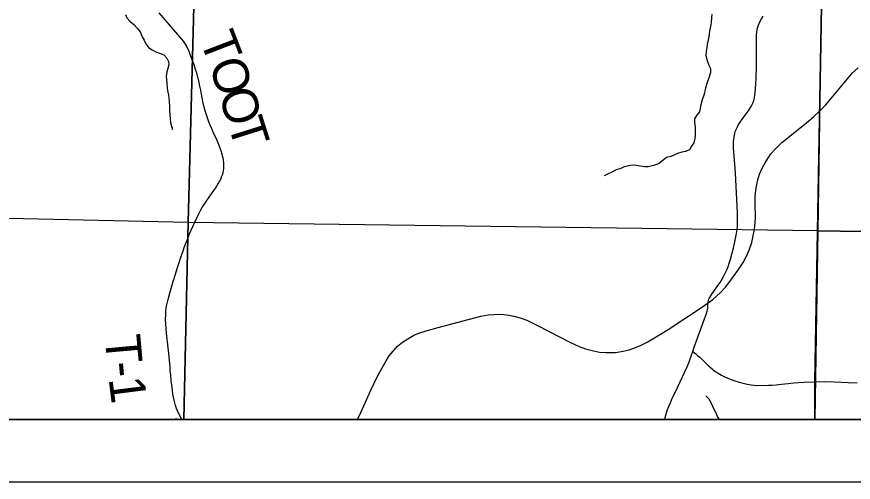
# Model space of a CAD drawing. Extents: x 0 to 34, y 0 to 22.
# Drawn here: x 15.148 to 16.483, y 13.5 to 14.243 of the extents above; entities that cross this region are included whole.
import ezdxf

# ---------------------------------------------------------------- set-up
doc = ezdxf.new("R2010")
doc.units = 0
for name, color, linetype in [('GM_X_Corporation', 7, 'Continuous'), ('GM_X_County_Road', 7, 'Continuous'), ('GM_X_Minor_River', 7, 'Continuous'), ('GM_X_Rail_Line', 7, 'Continuous'), ('GM_X_Township_Road', 7, 'Continuous'), ('GM_X_Township_Road_Text', 7, 'Continuous'), ('SH_Data', 7, 'Continuous')]:
    doc.layers.add(name, color=color, linetype=linetype)

msp = doc.modelspace()

# ---------------------------------------------------------------- linework, layer by layer
at = {"layer": 'GM_X_Corporation'}
for points in [[(16.4214, 13.6), (17.4, 13.6), (17.4, 16.913), (16.5516, 16.9243), (16.4689, 16.9245), (16.4603, 16.2617), (16.4611, 16.1288), (16.4516, 15.5964), (16.4498, 15.4626), (16.4419, 14.8642), (16.438, 14.5908), (16.4339, 14.3806), (16.4212, 13.6609)], [(14.443, 14.9501), (15.4475, 14.9085), (15.4212, 13.9143), (14.4181, 13.9369)], [(15.4475, 14.9085), (16.441, 14.8856), (16.4262, 13.901), (15.4212, 13.9143)], [(17.4, 13.8871), (17.4, 14.8906), (16.441, 14.8856), (16.4262, 13.901)], [(14.411, 13.6), (15.4145, 13.6), (15.4212, 13.9143), (14.4181, 13.9369)], [(15.4145, 13.6), (16.4212, 13.6), (16.4262, 13.901), (15.4212, 13.9143)], [(16.4212, 13.6), (17.4, 13.6), (17.4, 13.8871), (16.4262, 13.901)]]:
    msp.add_lwpolyline(points, close=True, dxfattribs=at)
msp.add_lwpolyline([(10.9052, 15.3502), (10.897, 14.5214), (10.8818, 13.7678), (10.8788, 13.6), (16.4214, 13.6), (16.4212, 13.6609), (16.4339, 14.3806), (16.438, 14.5908), (16.4419, 14.8642), (16.4498, 15.4626)], dxfattribs=at)
at = {"layer": 'GM_X_County_Road'}
msp.add_lwpolyline([(16.1817, 13.6), (16.1826, 13.6034), (16.1859, 13.6143), (16.1882, 13.6207), (16.1907, 13.6268), (16.1944, 13.6352), (16.1982, 13.6433), (16.2177, 13.6844), (16.2201, 13.6904), (16.222, 13.6953), (16.2235, 13.6995), (16.2251, 13.7043), (16.2265, 13.7086), (16.2289, 13.7154), (16.2453, 13.7606), (16.247, 13.7653), (16.2483, 13.7693), (16.2495, 13.7731), (16.2499, 13.7749), (16.2503, 13.7776), (16.2506, 13.78), (16.2507, 13.7858), (16.2514, 13.7898), (16.2523, 13.7924), (16.2533, 13.7945), (16.254, 13.7959), (16.2568, 13.8002), (16.262, 13.8075), (16.2666, 13.814), (16.27, 13.819), (16.2721, 13.8223), (16.275, 13.8273), (16.2776, 13.8324), (16.2812, 13.8403), (16.2829, 13.8445), (16.2848, 13.8495), (16.2868, 13.8559), (16.289, 13.8638), (16.2916, 13.8738), (16.2937, 13.8834), (16.2964, 13.8969), (16.2974, 13.9033), (16.2978, 13.9085), (16.298, 13.9113), (16.298, 13.9229), (16.2979, 13.9305), (16.2947, 13.9932), (16.2942, 14.0008), (16.2917, 14.0334), (16.2916, 14.036), (16.2917, 14.0443), (16.2919, 14.0469), (16.2924, 14.0511), (16.2934, 14.0563), (16.2944, 14.0595), (16.2955, 14.0627), (16.2971, 14.0662), (16.299, 14.0697), (16.301, 14.073), (16.3069, 14.0813), (16.3147, 14.092), (16.3172, 14.0955), (16.3189, 14.0982), (16.3208, 14.1017), (16.3222, 14.1051), (16.3237, 14.1093), (16.3248, 14.1136), (16.3255, 14.1177), (16.3259, 14.1214), (16.327, 14.1356), (16.3275, 14.1453), (16.328, 14.1622), (16.3281, 14.1968), (16.3284, 14.2141), (16.3288, 14.2186), (16.3298, 14.2246), (16.3313, 14.2295), (16.3322, 14.232), (16.3334, 14.2347), (16.3361, 14.2397), (16.3388, 14.244)], dxfattribs=at)
at = {"layer": 'GM_X_Minor_River'}
msp.add_line((15.3999, 13.6), (15.4026, 13.6022), dxfattribs=at)
for points in [[(15.3209, 14.2463), (15.3233, 14.241), (15.3284, 14.2355), (15.3346, 14.2307), (15.3397, 14.2247), (15.3444, 14.2188), (15.348, 14.2109), (15.3508, 14.2052), (15.3536, 14.1996), (15.3579, 14.194), (15.3637, 14.1899), (15.3694, 14.187), (15.3756, 14.1845), (15.3821, 14.182), (15.3871, 14.1768), (15.3899, 14.1712), (15.3904, 14.1659), (15.3887, 14.1601), (15.3873, 14.1548), (15.3863, 14.1479), (15.3865, 14.1426), (15.387, 14.1357), (15.3875, 14.1304), (15.3884, 14.1244), (15.3897, 14.1183), (15.3907, 14.1077), (15.3913, 14.0997), (15.3915, 14.0932), (15.392, 14.0864), (15.3926, 14.0792), (15.3931, 14.0739), (15.3947, 14.0682), (15.396, 14.0629), (15.3962, 14.0667)], [(16.2569, 14.2469), (16.2562, 14.2416), (16.256, 14.2339), (16.2547, 14.2271), (16.2533, 14.2206), (16.2527, 14.2152), (16.2511, 14.2049), (16.2493, 14.1992), (16.2487, 14.1938), (16.2477, 14.1873), (16.2471, 14.1808), (16.2496, 14.1729), (16.252, 14.1654), (16.2548, 14.1601), (16.255, 14.1536), (16.2529, 14.1467), (16.2486, 14.1345), (16.2465, 14.1268), (16.2448, 14.1195), (16.2416, 14.1103), (16.2396, 14.1023), (16.2382, 14.0969), (16.2372, 14.0912), (16.2324, 14.0854), (16.2291, 14.08), (16.2293, 14.0739), (16.2302, 14.0674), (16.2303, 14.0606), (16.2301, 14.0545), (16.2299, 14.0488), (16.2282, 14.0415), (16.2245, 14.0361), (16.2212, 14.0303), (16.2148, 14.0279), (16.2092, 14.0266), (16.202, 14.0245), (16.1915, 14.0197), (16.1847, 14.018), (16.1791, 14.014), (16.1717, 14.0082), (16.1638, 14.0053), (16.1555, 14.0032), (16.1494, 14.0034), (16.1361, 14.0057), (16.1304, 14.006), (16.124, 14.0047), (16.1172, 14.0034), (16.1116, 14.0006), (16.104, 13.9985), (16.0973, 13.9949), (16.0905, 13.9917), (16.0853, 13.9892)], [(16.2689, 13.6), (16.2659, 13.6047), (16.2631, 13.6114), (16.2603, 13.6174), (16.2571, 13.6246), (16.2527, 13.6325), (16.2473, 13.638)]]:
    msp.add_lwpolyline(points, dxfattribs=at)
at = {"layer": 'GM_X_Rail_Line'}
msp.add_lwpolyline([(15.6914, 13.6), (15.6967, 13.6112), (15.7127, 13.6472), (15.7227, 13.6682), (15.7327, 13.6865), (15.7372, 13.6939), (15.742, 13.7016), (15.7481, 13.7093), (15.7555, 13.7172), (15.7634, 13.7234), (15.7717, 13.729), (15.7814, 13.7346), (15.7925, 13.739), (15.8049, 13.7428), (15.826, 13.7486), (15.8884, 13.7648), (15.9002, 13.7671), (15.9097, 13.7678), (15.9174, 13.7681), (15.9252, 13.7677), (15.933, 13.7667), (15.941, 13.7652), (15.951, 13.7625), (15.9617, 13.7587), (15.9788, 13.7504), (16.0313, 13.723), (16.0454, 13.7168), (16.0554, 13.7128), (16.0683, 13.7095), (16.0776, 13.7076), (16.0876, 13.7069), (16.0945, 13.7069), (16.1034, 13.7072), (16.1152, 13.7091), (16.125, 13.7114), (16.1343, 13.7146), (16.1441, 13.7187), (16.1536, 13.7235), (16.163, 13.7289), (16.1874, 13.7439), (16.2419, 13.7797), (16.2587, 13.7918), (16.2707, 13.8026), (16.2786, 13.8114), (16.2859, 13.8201), (16.2985, 13.8377), (16.3069, 13.8507), (16.3124, 13.8609), (16.3166, 13.8705), (16.3205, 13.8824), (16.3231, 13.8931), (16.3251, 13.9031), (16.326, 13.9145), (16.3267, 13.9229), (16.3262, 13.9456), (16.3262, 13.955), (16.3269, 13.9663), (16.3285, 13.9751), (16.3306, 13.9828), (16.3332, 13.9918), (16.3374, 14.0011), (16.3418, 14.0097), (16.3463, 14.0167), (16.3511, 14.0239), (16.3571, 14.0306), (16.3626, 14.0363), (16.3684, 14.0421), (16.4078, 14.0737), (16.4197, 14.0838), (16.4288, 14.0923), (16.4382, 14.1016), (16.4471, 14.1118), (16.4732, 14.144), (16.4813, 14.1531), (16.4903, 14.1614)], dxfattribs=at)
at = {"layer": 'GM_X_Township_Road'}
for points in [[(15.4106, 13.6), (15.4098, 13.6015), (15.4048, 13.6127), (15.4028, 13.6177), (15.4011, 13.6224), (15.3999, 13.6266), (15.3988, 13.631), (15.3977, 13.6358), (15.3969, 13.6404), (15.3961, 13.6461), (15.3954, 13.6515), (15.3943, 13.6619), (15.3934, 13.6707), (15.3927, 13.6779), (15.3922, 13.6839), (15.3901, 13.7057), (15.387, 13.7331), (15.3865, 13.7377), (15.3854, 13.7527), (15.3851, 13.7589), (15.3853, 13.7687), (15.3856, 13.7732), (15.3861, 13.7778), (15.3865, 13.781), (15.3881, 13.7875), (15.3897, 13.794), (15.3919, 13.8017), (15.3973, 13.8201), (15.4009, 13.8319), (15.4038, 13.8413), (15.4068, 13.8506), (15.4092, 13.8577), (15.4131, 13.8694), (15.4154, 13.8761), (15.4204, 13.8891), (15.4229, 13.8951), (15.4314, 13.9138), (15.4373, 13.9261), (15.4416, 13.9345), (15.4436, 13.9383), (15.4486, 13.9463), (15.4508, 13.9496), (15.4622, 13.9656), (15.4651, 13.9698), (15.4693, 13.9764), (15.4712, 13.9798), (15.4731, 13.9839), (15.4746, 13.9873), (15.4763, 13.9918), (15.4774, 13.9963), (15.4782, 14.0017), (15.4783, 14.0044), (15.4782, 14.0092), (15.4775, 14.0144), (15.4771, 14.0173), (15.4751, 14.0249), (15.4744, 14.0273), (15.4697, 14.0399), (15.4674, 14.0453), (15.4658, 14.0489), (15.4618, 14.0573), (15.4587, 14.0641), (15.4568, 14.0685), (15.4542, 14.0751), (15.4526, 14.0799), (15.4488, 14.0909), (15.4465, 14.0983), (15.4444, 14.1074), (15.4433, 14.1136), (15.4423, 14.1195), (15.4412, 14.1256), (15.4399, 14.1321), (15.438, 14.1405), (15.4366, 14.146), (15.4353, 14.151), (15.4331, 14.1584), (15.4307, 14.1659), (15.4288, 14.1713), (15.4245, 14.1827), (15.4226, 14.1873), (15.4183, 14.1964), (15.4167, 14.1992), (15.4138, 14.2037), (15.4113, 14.2069), (15.3749, 14.2493)], [(16.2265, 13.7086), (16.229, 13.7066), (16.2315, 13.7048), (16.2341, 13.7025), (16.2377, 13.6995), (16.2398, 13.6975), (16.2513, 13.6861), (16.2536, 13.684), (16.2579, 13.6804), (16.2624, 13.677), (16.267, 13.6739), (16.2721, 13.6708), (16.2762, 13.6687), (16.2824, 13.6659), (16.2862, 13.6643), (16.2934, 13.6617), (16.3003, 13.6596), (16.3067, 13.6579), (16.3133, 13.6564), (16.3197, 13.6554), (16.3241, 13.655), (16.3297, 13.6546), (16.3471, 13.6549), (16.3527, 13.6551), (16.3594, 13.6556), (16.3681, 13.6564), (16.3788, 13.6578), (16.3879, 13.6587), (16.3953, 13.6593), (16.4045, 13.6597), (16.421, 13.6601)], [(16.421, 13.6601), (16.4363, 13.6606), (16.4518, 13.6605), (16.4743, 13.6594), (16.4891, 13.6588)]]:
    msp.add_lwpolyline(points, dxfattribs=at)
at = {"layer": 'SH_Data'}
for points in [[(10.5, 20.5), (17.5, 20.5), (17.5, 13.5), (10.5, 13.5)], [(10.6, 20.4), (17.4, 20.4), (17.4, 13.6), (10.6, 13.6)]]:
    msp.add_lwpolyline(points, close=True, dxfattribs=at)

# ---------------------------------------------------------------- texts
at = {"layer": 'GM_X_Township_Road_Text'}
for s, rotation, p in [('T', 290.9944, (15.4388, 14.2067)), ('O', 287.7265, (15.4537, 14.1679)), ('O', 287.4592, (15.4689, 14.1203)), ('T', 287.4537, (15.4839, 14.0726)), ('T', 275.1281, (15.2878, 13.7333)), ('-', 275.4902, (15.2917, 13.6906)), ('1', 277.259, (15.2941, 13.6654))]:
    msp.add_text(s, height=0.0568, rotation=rotation, dxfattribs=at).set_placement(p)

doc.saveas('drawing.dxf')
